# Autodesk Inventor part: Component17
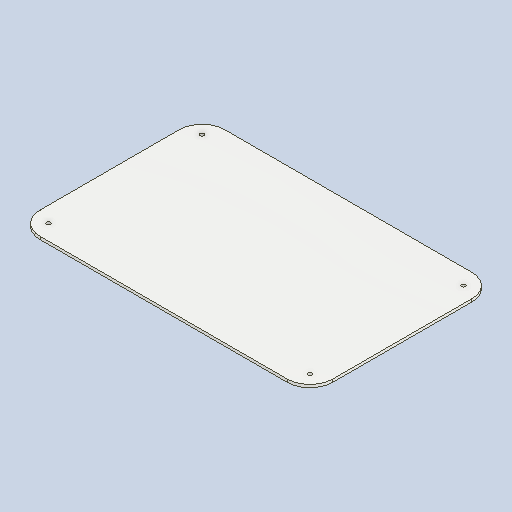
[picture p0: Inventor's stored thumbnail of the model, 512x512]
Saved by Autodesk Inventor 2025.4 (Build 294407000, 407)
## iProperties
Created: 2026-06
Part Number: Component17
Material: Generic
Document SubType Name: Modeling
Designer: AdminForWorker
Density: 1 g/cm^3
Appearance: Default
Title: Component17
Author: AdminForWorker
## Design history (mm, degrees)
feature "Body1"
body "Solid1"
